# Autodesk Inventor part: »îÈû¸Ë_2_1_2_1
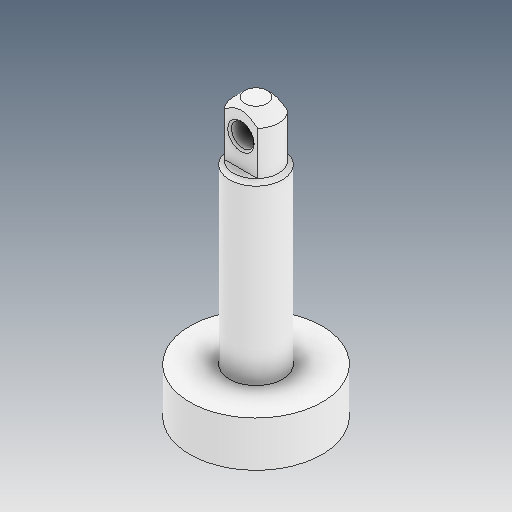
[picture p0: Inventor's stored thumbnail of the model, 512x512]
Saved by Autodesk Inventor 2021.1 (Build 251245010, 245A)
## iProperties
Created: 2021-05
Part Number: »îÈû¸Ë_2_1_2_1
Material: Ogólny
Document SubType Name: Modeling
Designer: user
Density: 1 g/cm^3
Appearance: Domyślna
Author: user
Revision Number: ÈÎºÎ
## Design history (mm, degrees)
feature "ÊäÈë1"
node "Bryła1"
